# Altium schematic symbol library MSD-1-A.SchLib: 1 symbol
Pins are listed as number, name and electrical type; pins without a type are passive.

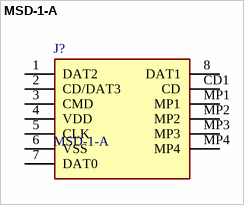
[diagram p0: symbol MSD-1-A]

## MSD-1-A
designator J?
Memory Card Connectors 9 Positions, Push In, Auto Eject Out, SMT, 1.8 mm Height Above Board,; Manufacturer_Name: CUI Devices; Geometry.Height: 2mm
footprint MSD1A
pins: 1 DAT2, 2 CD/DAT3, 3 CMD, 4 VDD, 5 CLK, 6 VSS, 7 DAT0, 8 DAT1, CD1 CD, MP1, MP2, MP3, MP4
